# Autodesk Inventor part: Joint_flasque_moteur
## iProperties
Shininess: 64.0
Length Units: 11269
Angle Units: 11279
Time Units: 11290
Mass Units: 11283
Length Display Precision: 3
Angle Display Precision: 2
Compacted: True
Part Number: Joint_flasque_moteur
Document SubType Name: Modeling
Created: 2008-02
Material: UHMW - Noir
Designer: Pascal
Density: 0.0
Volumn: 0.0
Area: 0.0
PropertySet Name: Model Information
Control State: 0
Master: False
Checked Out: False
DESIGNATION: Joint flasque corps
Author: Pascal
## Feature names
1. Extrusion1
2. Extrusion2
3. Réseau circulaire1 [Circular Pattern]
4. Extrusion3
